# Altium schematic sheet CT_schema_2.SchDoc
size 388 x 258 mm
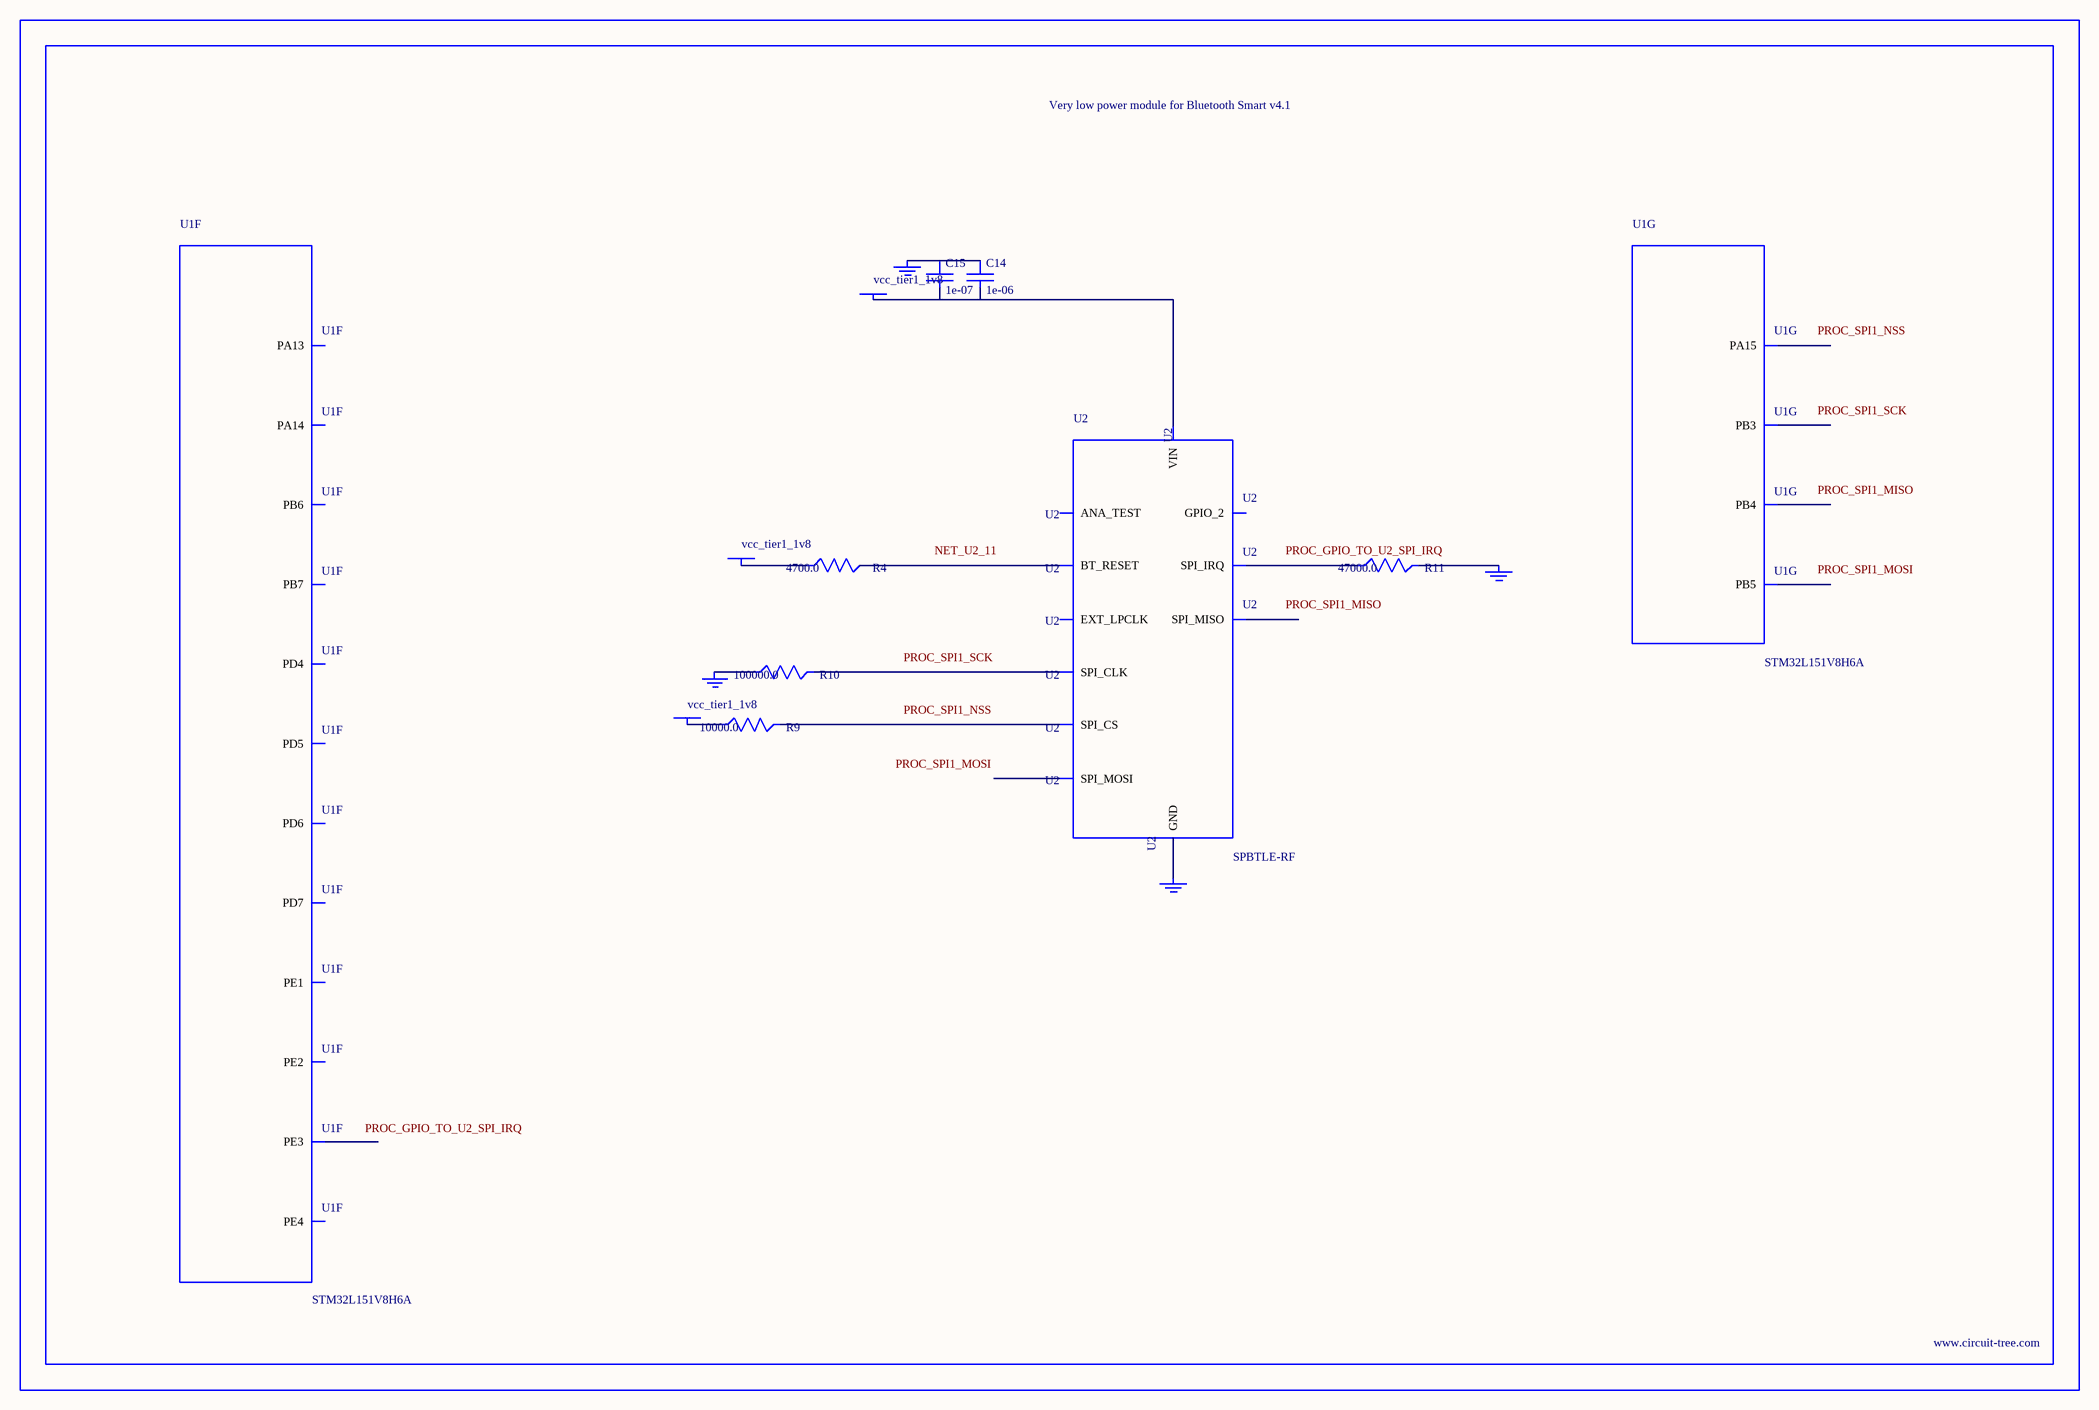
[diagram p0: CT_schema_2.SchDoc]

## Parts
BORDER1  (no value)
C14  1e-06  [C0603]
C15  1e-07  [C0402]
GND_INSTANCE_1_0  (no value)
GND_INSTANCE_1_1  (no value)
GND_INSTANCE_1_2  (no value)
GND_INSTANCE_1_3  (no value)
POWER_INSTANCE_1_0  vcc_tier1_1v8
POWER_INSTANCE_1_1  vcc_tier1_1v8
POWER_INSTANCE_1_2  vcc_tier1_1v8
R4  4700.0  [R0603]
R9  10000.0  [R0603]
R10  100000.0  [R0603]
R11  47000.0  [R0603]
U1  STM32L151V8H6A  [UFBGA100]  (parts F,G of 9)
U2  SPBTLE-RF  [XCVR_SPBTLE-RF]

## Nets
NetC14_1: C14.1 C15.1 GND_INSTANCE_1_1.0(GND)
NetC14_2: C14.2 C15.2 POWER_INSTANCE_1_0.0(PWR) U2.5(VIN)
NetGND_INSTANCE_1_0_0: GND_INSTANCE_1_0.0(GND) R11.2
NetGND_INSTANCE_1_2_0: GND_INSTANCE_1_2.0(GND) R10.1
NetGND_INSTANCE_1_3_0: GND_INSTANCE_1_3.0(GND) U2.6(GND)
NetPOWER_INSTANCE_1_1_0: POWER_INSTANCE_1_1.0(PWR) R9.1
NetPOWER_INSTANCE_1_2_0: POWER_INSTANCE_1_2.0(PWR) R4.1
NetR4_2: R4.2 U2.11(BT_RESET)
NetR9_2: R9.2 U2.10(SPI_CS)
NetR10_2: R10.2 U2.7(SPI_CLK)
NetR11_1: R11.1 U2.4(SPI_IRQ)

Not connected (* = marked no-connect by the designer): U1 A1(PE3) A2(PE1) A5(PD7) A6(PD5) A7(PB4) A8(PB3) A9(PA15) A10(PA14) A11(PA13) B1(PE4) B2(PE2) B4(PB7) B5(PB6) B6(PD6) B7(PD4) C5(PB5); U2 1(EXT_LPCLK) 2(GPIO_2) 3(ANA_TEST) 8(SPI_MISO) 9(SPI_MOSI)

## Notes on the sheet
- Labels drawn without touching a wire or pin: NET_U2_11, PROC_GPIO_TO_U2_SPI_IRQ, PROC_SPI1_MISO, PROC_SPI1_MOSI, PROC_SPI1_NSS, PROC_SPI1_SCK

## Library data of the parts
BORDER1 = BORDER_PAGE1
C14 = C0603C105K3RACTU
C15 = C0402C104K3RACTU
GND_INSTANCE_1_0-GND_INSTANCE_1_3 = GND
POWER_INSTANCE_1_0-POWER_INSTANCE_1_2 = PWR
R4 = RC0603JR-074K7L
R9 = RC0603JR-0710KL
R10 = RC0603JR-07100KL
R11 = RC0603JR-0747KL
